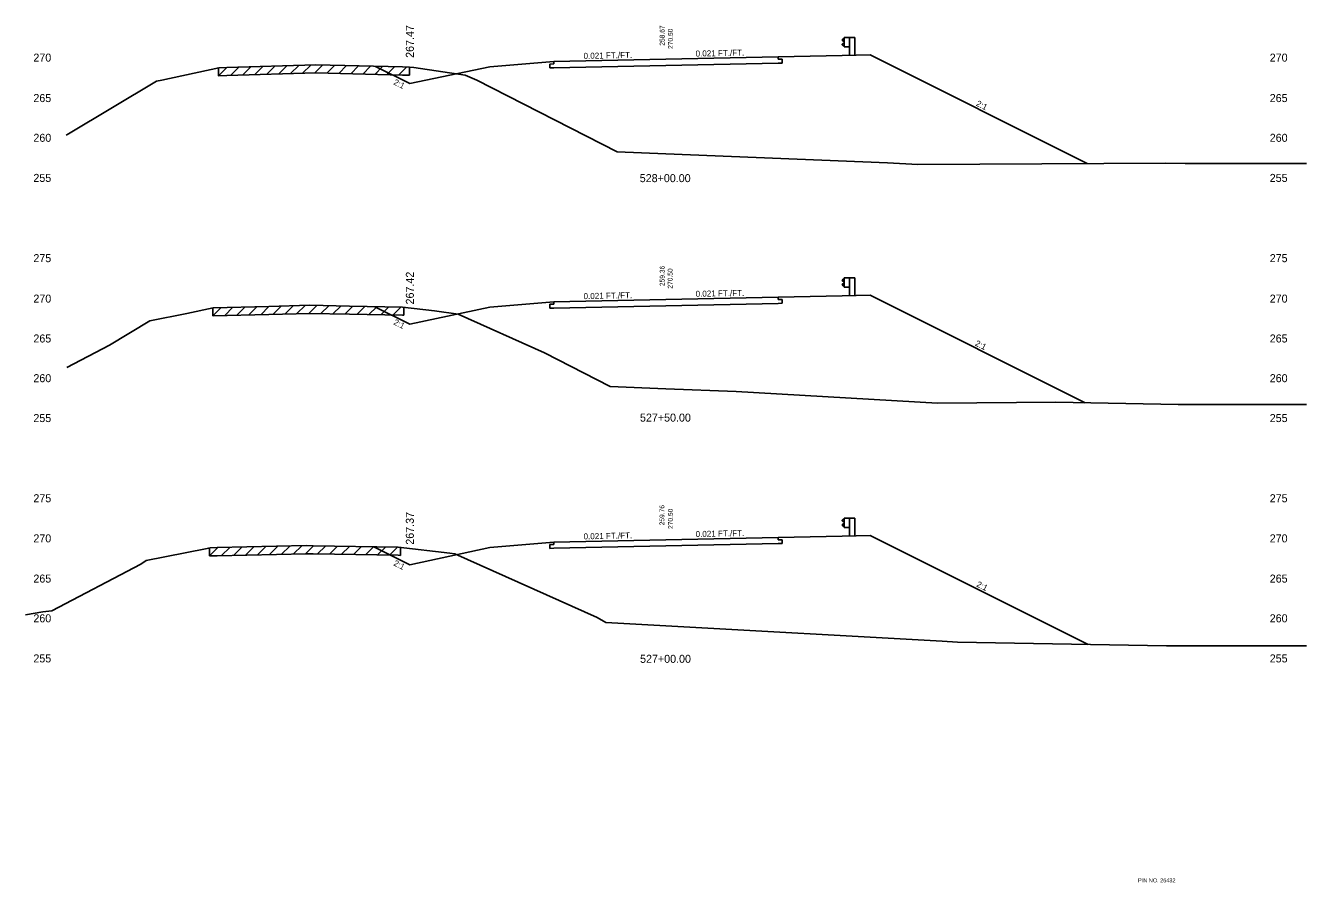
# Model space of a CAD drawing. Extents: x 883 to 1160, y 1002 to 4323.
# Drawn here: x 1000 to 1160, y 3287.7 to 3394.7 of the extents above; entities that cross this region are included whole.
import ezdxf

# ---------------------------------------------------------------- set-up
doc = ezdxf.new("R2010")
doc.units = 0
for name, color, linetype in [('Level 1', 7, 'Continuous'), ('Level 10', 7, 'Continuous'), ('Level 11', 7, 'Continuous'), ('Level 12', 7, 'Continuous'), ('Level 24', 7, 'Continuous'), ('Level 3', 7, 'Continuous'), ('Level 32', 7, 'Continuous'), ('Level 33', 7, 'Continuous'), ('Level 59', 7, 'Continuous'), ('Level 6', 7, 'Continuous'), ('Level 60', 7, 'Continuous'), ('Level 61', 7, 'Continuous'), ('Level 7', 7, 'Continuous')]:
    doc.layers.add(name, color=color, linetype=linetype)

msp = doc.modelspace()

# ---------------------------------------------------------------- linework, layer by layer
at = {"layer": 'Level 11'}
for p, q in [((1094, 3390.49), (1094, 3390.79)), ((1094.5, 3390.5), (1094, 3390.49)), ((1094.5, 3390.02), (1094.5, 3390.5)), ((1066, 3389.91), (1065.5, 3389.9)), ((1065.5, 3389.9), (1065.5, 3389.42)), ((1065.5, 3389.42), (1066, 3389.43)), ((1066, 3390.21), (1066, 3389.91)), ((1094, 3390.01), (1094.5, 3390.02)), ((1066, 3360.21), (1066, 3359.91)), ((1094, 3360.49), (1094, 3360.79)), ((1094.5, 3360.5), (1094, 3360.49)), ((1094, 3360.01), (1094.5, 3360.02)), ((1094.5, 3360.02), (1094.5, 3360.5)), ((1066, 3359.91), (1065.5, 3359.9)), ((1065.5, 3359.9), (1065.5, 3359.42)), ((1065.5, 3359.42), (1066, 3359.43)), ((1066, 3329.91), (1065.5, 3329.9)), ((1065.5, 3329.9), (1065.5, 3329.42)), ((1066, 3330.21), (1066, 3329.91)), ((1094, 3330.49), (1094, 3330.79)), ((1094.5, 3330.5), (1094, 3330.49)), ((1094, 3330.01), (1094.5, 3330.02)), ((1094.5, 3330.02), (1094.5, 3330.5)), ((1065.5, 3329.42), (1066, 3329.43))]:
    msp.add_line(p, q, dxfattribs=at)
at = {"layer": 'Level 12'}
for p, q in [((1080, 3389.72), (1066, 3389.43)), ((1094, 3390.01), (1080, 3389.72)), ((1094, 3360.01), (1080, 3359.72)), ((1080, 3359.72), (1066, 3359.43)), ((1080, 3329.72), (1066, 3329.43)), ((1094, 3330.01), (1080, 3329.72))]:
    msp.add_line(p, q, dxfattribs=at)
at = {"layer": 'Level 24'}
for p, q in [((1102.27, 3393.13), (1102, 3392.93)), ((1102, 3392.93), (1102, 3392.88)), ((1102, 3392.88), (1102.27, 3392.68)), ((1102, 3392.36), (1102.27, 3392.56)), ((1102, 3392.31), (1102, 3392.36)), ((1102.27, 3392.11), (1102, 3392.31)), ((1102.27, 3392.04), (1102.27, 3393.21)), ((1102.27, 3393.21), (1102.94, 3393.21)), ((1102.27, 3392.04), (1102.94, 3392.04)), ((1102.94, 3393.21), (1102.94, 3390.98)), ((1102.94, 3393.21), (1103.6, 3393.21)), ((1103.6, 3393.21), (1103.6, 3390.99)), ((1102.27, 3362.04), (1102.27, 3363.21)), ((1102.27, 3363.21), (1102.94, 3363.21)), ((1102.94, 3363.21), (1102.94, 3360.98)), ((1102.94, 3363.21), (1103.6, 3363.21)), ((1103.6, 3363.21), (1103.6, 3360.99)), ((1102.27, 3363.13), (1102, 3362.93)), ((1102, 3362.93), (1102, 3362.88)), ((1102, 3362.88), (1102.27, 3362.68)), ((1102, 3362.36), (1102.27, 3362.56)), ((1102, 3362.31), (1102, 3362.36)), ((1102.27, 3362.11), (1102, 3362.31)), ((1102.27, 3362.04), (1102.94, 3362.04)), ((1102.27, 3333.13), (1102, 3332.93)), ((1102, 3332.93), (1102, 3332.88)), ((1102, 3332.88), (1102.27, 3332.68)), ((1102.27, 3332.04), (1102.27, 3333.21)), ((1102.27, 3333.21), (1102.94, 3333.21)), ((1102.94, 3333.21), (1102.94, 3330.98)), ((1102.94, 3333.21), (1103.6, 3333.21)), ((1103.6, 3333.21), (1103.6, 3330.99)), ((1102, 3332.36), (1102.27, 3332.56)), ((1102, 3332.31), (1102, 3332.36)), ((1102.27, 3332.11), (1102, 3332.31)), ((1102.27, 3332.04), (1102.94, 3332.04))]:
    msp.add_line(p, q, dxfattribs=at)
at = {"layer": 'Level 59'}
for p, q in [((1066, 3390.21), (1080, 3390.5)), ((1080, 3390.5), (1094, 3390.79)), ((1066, 3360.21), (1080, 3360.5)), ((1080, 3360.5), (1094, 3360.79)), ((1066, 3330.21), (1080, 3330.5)), ((1080, 3330.5), (1094, 3330.79))]:
    msp.add_line(p, q, dxfattribs=at)
at = {"layer": 'Level 6'}
for p, q in [((1094, 3390.79), (1102, 3390.96)), ((1102, 3390.96), (1105.5, 3391.03)), ((1058, 3389.54), (1066, 3390.21)), ((1058, 3359.54), (1066, 3360.21)), ((1094, 3360.79), (1102, 3360.96)), ((1102, 3360.96), (1105.5, 3361.03)), ((1058, 3329.54), (1066, 3330.21)), ((1094, 3330.79), (1102, 3330.96)), ((1102, 3330.96), (1105.5, 3331.03))]:
    msp.add_line(p, q, dxfattribs=at)
at = {"layer": 'Level 60'}
for p, q in [((1017.01, 3387.89), (1024.15, 3389.44)), ((1024.15, 3389.44), (1025.13, 3389.47)), ((1025.13, 3389.47), (1036.27, 3389.79)), ((1036.27, 3389.79), (1047.07, 3389.53)), ((1047.07, 3389.53), (1047.95, 3389.51)), ((1047.95, 3389.51), (1048.49, 3389.45)), ((1048.49, 3389.45), (1054.91, 3388.52)), ((1005.37, 3381.18), (1016.34, 3387.76)), ((1016.34, 3387.76), (1017.01, 3387.89)), ((1054.91, 3388.52), (1056.37, 3387.87)), ((1056.37, 3387.87), (1073.9, 3378.92)), ((1005.08, 3381.03), (1005.37, 3381.18)), ((1073.9, 3378.92), (1080, 3378.67)), ((1080, 3378.67), (1107.68, 3377.56)), ((1107.68, 3377.56), (1111.47, 3377.34)), ((1111.47, 3377.34), (1142.43, 3377.53)), ((1142.43, 3377.53), (1144.86, 3377.48)), ((1144.86, 3377.48), (1160, 3377.48)), ((1015.52, 3357.85), (1020.15, 3358.76)), ((1020.15, 3358.76), (1023.44, 3359.47)), ((1023.44, 3359.47), (1030.37, 3359.62)), ((1030.37, 3359.62), (1035.5, 3359.77)), ((1035.5, 3359.77), (1040.46, 3359.65)), ((1040.46, 3359.65), (1047.08, 3359.54)), ((1047.08, 3359.54), (1051.06, 3359.09)), ((1051.06, 3359.09), (1054.03, 3358.66)), ((1054.03, 3358.66), (1064.82, 3353.83)), ((1010.46, 3354.81), (1015.52, 3357.85)), ((1005.14, 3352.02), (1010.46, 3354.81)), ((1064.82, 3353.83), (1073.02, 3349.64)), ((1073.02, 3349.64), (1080, 3349.36)), ((1080, 3349.36), (1088.76, 3349.01)), ((1088.76, 3349.01), (1113.93, 3347.57)), ((1113.93, 3347.57), (1128.71, 3347.66)), ((1128.71, 3347.66), (1143.98, 3347.38)), ((1143.98, 3347.38), (1152.75, 3347.38)), ((1152.75, 3347.38), (1160, 3347.38)), ((1023.92, 3329.51), (1035.05, 3329.76)), ((1035.05, 3329.76), (1035.91, 3329.74)), ((1035.91, 3329.74), (1046.55, 3329.56)), ((1015.05, 3327.91), (1022.48, 3329.37)), ((1022.48, 3329.37), (1023.05, 3329.48)), ((1023.05, 3329.48), (1023.92, 3329.51)), ((1046.55, 3329.56), (1053.01, 3328.83)), ((1053.01, 3328.83), (1053.63, 3328.75)), ((1053.63, 3328.75), (1071.42, 3320.78)), ((1003.27, 3321.61), (1014.39, 3327.45)), ((1014.39, 3327.45), (1015.05, 3327.91)), ((1002.17, 3321.48), (1003.27, 3321.61)), ((1000, 3321.12), (1002.17, 3321.48)), ((1071.42, 3320.78), (1072.48, 3320.18)), ((1072.48, 3320.18), (1080, 3319.76)), ((1080, 3319.76), (1114.51, 3317.82)), ((1114.51, 3317.82), (1116.4, 3317.71)), ((1116.4, 3317.71), (1142.52, 3317.25)), ((1142.52, 3317.25), (1143.43, 3317.24)), ((1143.43, 3317.24), (1144.08, 3317.24)), ((1144.08, 3317.24), (1160, 3317.26))]:
    msp.add_line(p, q, dxfattribs=at)
at = {"layer": 'Level 61'}
for p, q in [((1025.14, 3389.47), (1024.11, 3388.44)), ((1024.11, 3389.44), (1024.11, 3388.44)), ((1026.64, 3389.51), (1025.61, 3388.48)), ((1028.14, 3389.55), (1027.11, 3388.52)), ((1029.64, 3389.6), (1028.61, 3388.57)), ((1031.14, 3389.64), (1030.11, 3388.61)), ((1032.64, 3389.68), (1031.61, 3388.65)), ((1034.14, 3389.73), (1033.11, 3388.7)), ((1035.64, 3389.77), (1034.61, 3388.74)), ((1037.09, 3389.77), (1036.11, 3388.78)), ((1038.59, 3389.73), (1037.61, 3388.76)), ((1040.09, 3389.7), (1039.11, 3388.72)), ((1041.59, 3389.66), (1040.61, 3388.68)), ((1043.09, 3389.62), (1042.11, 3388.65)), ((1044.59, 3389.59), (1043.61, 3388.61)), ((1046.09, 3389.55), (1045.11, 3388.58)), ((1047.59, 3389.52), (1046.61, 3388.54)), ((1047.96, 3388.51), (1047.96, 3389.51)), ((1024.11, 3388.44), (1024.15, 3388.44)), ((1024.15, 3388.44), (1025.13, 3388.47)), ((1025.13, 3388.47), (1036.27, 3388.79)), ((1036.27, 3388.79), (1047.07, 3388.53)), ((1047.07, 3388.53), (1047.95, 3388.51)), ((1047.95, 3388.51), (1047.96, 3388.51)), ((1024.41, 3359.49), (1023.38, 3358.46)), ((1023.38, 3359.46), (1023.38, 3358.46)), ((1023.38, 3358.46), (1023.44, 3358.47)), ((1023.44, 3358.47), (1030.37, 3358.62)), ((1025.9, 3359.52), (1024.88, 3358.5)), ((1027.4, 3359.56), (1026.38, 3358.54)), ((1028.9, 3359.59), (1027.88, 3358.57)), ((1030.4, 3359.63), (1029.38, 3358.6)), ((1030.37, 3358.62), (1035.5, 3358.77)), ((1031.91, 3359.67), (1030.88, 3358.64)), ((1033.41, 3359.71), (1032.38, 3358.68)), ((1034.91, 3359.76), (1033.88, 3358.73)), ((1036.36, 3359.75), (1035.38, 3358.77)), ((1035.5, 3358.77), (1040.46, 3358.65)), ((1037.86, 3359.72), (1036.88, 3358.74)), ((1039.36, 3359.68), (1038.38, 3358.7)), ((1040.86, 3359.65), (1039.88, 3358.67)), ((1040.46, 3358.65), (1047.08, 3358.54)), ((1042.36, 3359.62), (1041.38, 3358.64)), ((1043.86, 3359.6), (1042.88, 3358.61)), ((1045.36, 3359.57), (1044.38, 3358.59)), ((1046.86, 3359.55), (1045.88, 3358.56)), ((1047.08, 3358.54), (1047.23, 3358.53)), ((1047.23, 3358.53), (1047.23, 3359.53)), ((1028.5, 3329.61), (1027.47, 3328.59)), ((1030, 3329.64), (1028.97, 3328.62)), ((1031.5, 3329.68), (1030.47, 3328.65)), ((1033, 3329.71), (1031.97, 3328.69)), ((1034.5, 3329.74), (1033.47, 3328.72)), ((1035.96, 3329.74), (1034.97, 3328.75)), ((1037.46, 3329.71), (1036.47, 3328.73)), ((1038.96, 3329.69), (1037.97, 3328.7)), ((1040.46, 3329.66), (1039.47, 3328.68)), ((1041.96, 3329.64), (1040.97, 3328.65)), ((1043.46, 3329.61), (1042.47, 3328.63)), ((1024.01, 3329.51), (1022.97, 3328.47)), ((1022.97, 3329.47), (1022.97, 3328.47)), ((1022.97, 3328.47), (1023.05, 3328.48)), ((1023.05, 3328.48), (1023.92, 3328.51)), ((1023.92, 3328.51), (1035.05, 3328.76)), ((1025.5, 3329.54), (1024.47, 3328.52)), ((1027, 3329.57), (1025.97, 3328.55)), ((1035.05, 3328.76), (1035.91, 3328.74)), ((1035.91, 3328.74), (1046.55, 3328.56)), ((1044.96, 3329.59), (1043.97, 3328.6)), ((1046.46, 3329.56), (1045.47, 3328.58)), ((1046.55, 3328.56), (1046.82, 3328.53)), ((1046.82, 3328.53), (1046.82, 3329.53))]:
    msp.add_line(p, q, dxfattribs=at)
at = {"layer": 'Level 7'}
for p, q in [((1105.5, 3391.03), (1132.63, 3377.47)), ((1043.71, 3389.61), (1048, 3387.47)), ((1048, 3387.47), (1058, 3389.54)), ((1105.5, 3361.03), (1132.38, 3347.59)), ((1043.63, 3359.6), (1048, 3357.42)), ((1048, 3357.42), (1058, 3359.54)), ((1043.51, 3329.61), (1048, 3327.37)), ((1105.5, 3331.03), (1132.72, 3317.42)), ((1048, 3327.37), (1058, 3329.54))]:
    msp.add_line(p, q, dxfattribs=at)

# ---------------------------------------------------------------- texts
at = {"layer": 'Level 1'}
for s, height, p in [('528+00.00', 1, (1076.72, 3375.15)), ('527+50.00', 1, (1076.75, 3345.25)), ('527+00.00', 1, (1076.76, 3315.13)), ('PIN NO. 26432', 0.5, (1138.97, 3287.72))]:
    msp.add_text(s, height=height, dxfattribs=at).set_placement(p)
at = {"layer": 'Level 10'}
for s, p in [('258.67', (1079.82, 3392.19)), ('259.36', (1079.82, 3362.17)), ('259.76', (1079.79, 3332.3))]:
    msp.add_text(s, height=0.6, rotation=90, dxfattribs=at).set_placement(p)
at = {"layer": 'Level 3'}
for s, p in [(' 270', (1000.6, 3390.2)), (' 270', (1155.05, 3390.2)), (' 265', (1000.6, 3385.15)), (' 265', (1155.05, 3385.15)), (' 260', (1000.6, 3380.19)), (' 260', (1155.05, 3380.19)), (' 255', (1000.6, 3375.18)), (' 255', (1155.05, 3375.18)), (' 275', (1000.6, 3365.16)), (' 275', (1155.05, 3365.16)), (' 270', (1000.6, 3360.11)), (' 270', (1155.05, 3360.11)), (' 265', (1000.6, 3355.13)), (' 265', (1155.05, 3355.13)), (' 260', (1000.6, 3350.17)), (' 260', (1155.05, 3350.17)), (' 255', (1000.6, 3345.19)), (' 255', (1155.05, 3345.19)), (' 275', (1000.6, 3335.18)), (' 275', (1155.05, 3335.18)), (' 270', (1000.6, 3330.17)), (' 270', (1155.05, 3330.17)), (' 265', (1000.6, 3325.15)), (' 265', (1155.05, 3325.15)), (' 260', (1000.6, 3320.19)), (' 260', (1155.05, 3320.19)), (' 255', (1000.6, 3315.18)), (' 255', (1155.05, 3315.18))]:
    msp.add_text(s, height=1, dxfattribs=at).set_placement(p)
at = {"layer": 'Level 32'}
for s, rotation, p in [('0.021 FT./FT.', 1.1916, (1069.71, 3390.54)), ('0.021 FT./FT.', 1.1916, (1083.71, 3390.83)), ('2:1', 333.435, (1045.89, 3387.39)), ('2:1', 333.435, (1118.67, 3384.73)), ('0.021 FT./FT.', 1.1916, (1083.71, 3360.83)), ('0.021 FT./FT.', 1.1916, (1069.71, 3360.54)), ('2:1', 333.435, (1045.89, 3357.42)), ('2:1', 333.435, (1118.54, 3354.79)), ('0.021 FT./FT.', 1.1916, (1069.71, 3330.54)), ('0.021 FT./FT.', 1.1916, (1083.71, 3330.83)), ('2:1', 333.435, (1045.89, 3327.33)), ('2:1', 333.435, (1118.71, 3324.7))]:
    msp.add_text(s, height=0.75, rotation=rotation, dxfattribs=at).set_placement(p)
at = {"layer": 'Level 33'}
for s, p in [('267.47', (1048.5, 3390.67)), ('267.42', (1048.5, 3359.88)), ('267.37', (1048.5, 3329.88))]:
    msp.add_text(s, height=1, rotation=90, dxfattribs=at).set_placement(p)
at = {"layer": 'Level 59'}
for p in [(1080.85, 3391.56), (1080.82, 3361.62), (1080.85, 3331.62)]:
    msp.add_text(' 270.50', height=0.6, rotation=90, dxfattribs=at).set_placement(p)

doc.saveas('drawing.dxf')
